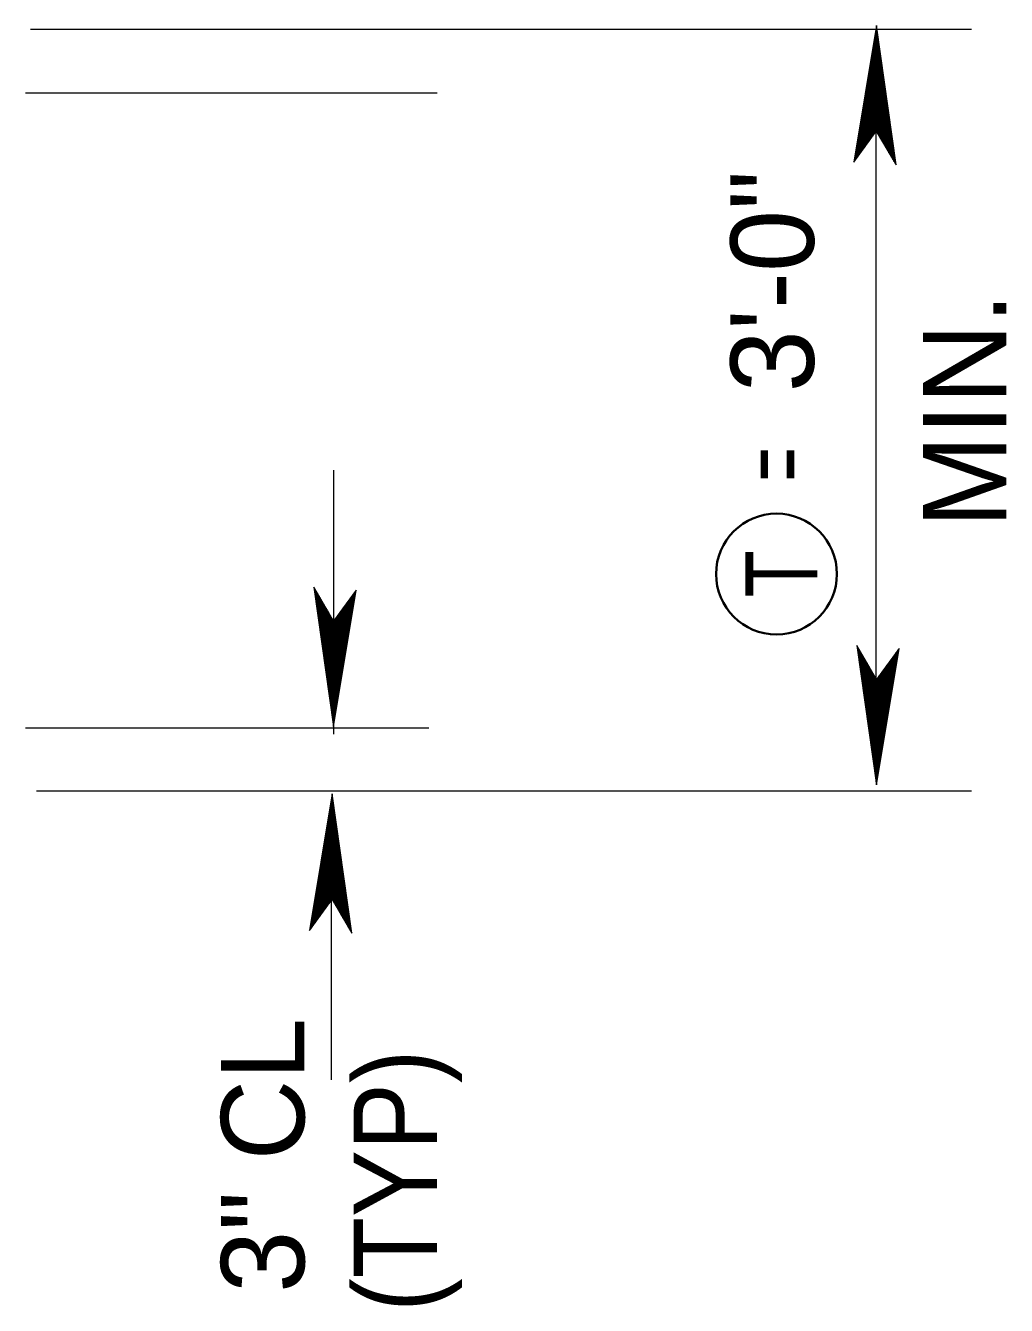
# Model space of a CAD drawing. Extents: x 144 to 252, y 360 to 425.
# Drawn here: x 198.94 to 202.8, y 367.72 to 372.76 of the extents above; entities that cross this region are included whole.
import ezdxf
from ezdxf.enums import TextEntityAlignment as Align

# ---------------------------------------------------------------- set-up
doc = ezdxf.new("R2010")
doc.units = 0
doc.header["$LTSCALE"] = 0.13
for name, color, linetype, lineweight in [('1', 7, 'Continuous', 40), ('16', 7, 'Continuous', 13), ('3', 7, 'Continuous', 13)]:
    doc.layers.add(name, color=color, linetype=linetype, lineweight=lineweight)

msp = doc.modelspace()

# ---------------------------------------------------------------- linework, layer by layer
at = {"layer": '1', "lineweight": 35}
msp.add_circle((201.8951, 370.5969), 0.238, dxfattribs=at)
at = {"layer": '3'}
for p, q in [((198.9573, 372.7427), (201.1462, 372.7427)), ((201.1462, 372.7427), (202.6627, 372.7427)), ((202.2882, 372.7568), (202.1989, 372.2191)), ((202.2875, 372.7423), (202.2012, 372.2223)), ((202.2875, 372.7315), (202.2036, 372.2256)), ((202.2875, 372.7171), (202.2067, 372.2298)), ((202.3624, 372.214), (202.2875, 372.7423)), ((202.3604, 372.2175), (202.2875, 372.7315)), ((202.3577, 372.2221), (202.2875, 372.7171)), ((202.2877, 369.7792), (202.2877, 372.7427)), ((202.2882, 372.3413), (202.2882, 372.7568)), ((202.3659, 372.208), (202.2882, 372.7568)), ((202.2875, 372.7043), (202.2094, 372.2336)), ((202.2875, 372.693), (202.2118, 372.2369)), ((202.2875, 372.6786), (202.215, 372.2412)), ((202.2875, 372.6658), (202.2177, 372.2449)), ((202.3553, 372.2262), (202.2875, 372.7043)), ((202.3553, 372.2262), (202.2875, 372.7043)), ((202.3532, 372.2298), (202.2875, 372.693)), ((202.3505, 372.2344), (202.2875, 372.6786)), ((202.3481, 372.2385), (202.2875, 372.6658)), ((202.2875, 372.6521), (202.2207, 372.249)), ((202.2875, 372.6382), (202.2237, 372.2531)), ((202.2875, 372.625), (202.2265, 372.257)), ((202.3456, 372.2429), (202.2875, 372.6521)), ((202.343, 372.2473), (202.2875, 372.6382)), ((202.3405, 372.2516), (202.2875, 372.625)), ((202.2875, 372.6111), (202.2295, 372.2611)), ((202.2875, 372.5985), (202.2322, 372.2648)), ((202.2875, 372.5871), (202.2347, 372.2682)), ((202.2875, 372.5714), (202.238, 372.2728)), ((202.3378, 372.2561), (202.2875, 372.6111)), ((202.3356, 372.2601), (202.2875, 372.5985)), ((202.3333, 372.2638), (202.2875, 372.5871)), ((202.3305, 372.2688), (202.2875, 372.5714)), ((202.2875, 372.5576), (202.241, 372.2769)), ((202.287, 372.5396), (202.2441, 372.2812)), ((202.287, 372.5257), (202.2471, 372.2853)), ((202.287, 372.5125), (202.2499, 372.2892)), ((202.3237, 372.2804), (202.287, 372.5396)), ((202.3211, 372.2848), (202.287, 372.5257)), ((202.3186, 372.2891), (202.287, 372.5125)), ((202.3278, 372.2732), (202.2875, 372.5576)), ((202.3256, 372.2772), (202.2886, 372.538)), ((198.9383, 372.4917), (200.5583, 372.4917)), ((202.2875, 372.5034), (202.2527, 372.2929)), ((202.2875, 372.4914), (202.2552, 372.2965)), ((202.2875, 372.4776), (202.2583, 372.3006)), ((202.2875, 372.4619), (202.2615, 372.3053)), ((202.3177, 372.2906), (202.2875, 372.5034)), ((202.3155, 372.2945), (202.2875, 372.4914)), ((202.3128, 372.2989), (202.2875, 372.4776)), ((202.31, 372.3039), (202.2875, 372.4619)), ((202.2875, 372.4493), (202.2643, 372.3089)), ((202.2875, 372.4361), (202.2671, 372.3128)), ((202.2875, 372.4241), (202.2697, 372.3164)), ((202.3076, 372.308), (202.2875, 372.4493)), ((202.3051, 372.3123), (202.2875, 372.4361)), ((202.3028, 372.3161), (202.2875, 372.4241)), ((202.2875, 372.4096), (202.2728, 372.3207)), ((202.2875, 372.3957), (202.2757, 372.3248)), ((202.2875, 372.3831), (202.2785, 372.3285)), ((202.2875, 372.3698), (202.2813, 372.3324)), ((202.3002, 372.3207), (202.2875, 372.4096)), ((202.2976, 372.3252), (202.2875, 372.3957)), ((202.2952, 372.3293), (202.2875, 372.3831)), ((202.2922, 372.3345), (202.2886, 372.3596)), ((202.1989, 372.2191), (202.288, 372.3416)), ((202.2875, 372.3584), (202.2837, 372.3358)), ((202.2875, 372.3483), (202.286, 372.3388)), ((202.2906, 372.3372), (202.2875, 372.3584)), ((202.288, 372.3416), (202.3659, 372.208)), ((200.1513, 371.0061), (200.1513, 369.9664)), ((200.0734, 370.5448), (200.1512, 369.9961)), ((200.1513, 370.4112), (200.0734, 370.5448)), ((200.0769, 370.5388), (200.1518, 370.0105)), ((200.0789, 370.5353), (200.1518, 370.0213)), ((200.0816, 370.5308), (200.1518, 370.0358)), ((200.084, 370.5267), (200.1518, 370.0485)), ((200.084, 370.5267), (200.1518, 370.0485)), ((200.0862, 370.523), (200.1518, 370.0598)), ((200.0888, 370.5184), (200.1518, 370.0743)), ((200.0913, 370.5143), (200.1518, 370.087)), ((200.0938, 370.5099), (200.1518, 370.1008)), ((200.0963, 370.5055), (200.1518, 370.1146)), ((200.0988, 370.5012), (200.1518, 370.1278)), ((200.1015, 370.4967), (200.1518, 370.1418)), ((200.1512, 369.9961), (200.2404, 370.5337)), ((200.2404, 370.5337), (200.1513, 370.4112)), ((200.1518, 370.0105), (200.2381, 370.5305)), ((200.1518, 370.0213), (200.2357, 370.5272)), ((200.1518, 370.0358), (200.2326, 370.523)), ((200.1518, 370.0485), (200.2299, 370.5192)), ((200.1518, 370.0598), (200.2275, 370.5159)), ((200.1518, 370.0743), (200.2243, 370.5117)), ((200.1518, 370.087), (200.2216, 370.5079)), ((200.1518, 370.1008), (200.2187, 370.5038)), ((200.1518, 370.1146), (200.2157, 370.4998)), ((200.1518, 370.1278), (200.2128, 370.4958)), ((200.1037, 370.4928), (200.1518, 370.1543)), ((200.106, 370.489), (200.1518, 370.1658)), ((200.1088, 370.484), (200.1518, 370.1814)), ((200.1115, 370.4796), (200.1518, 370.1952)), ((200.1137, 370.4756), (200.1507, 370.2148)), ((200.1157, 370.4724), (200.1523, 370.2132)), ((200.1182, 370.468), (200.1523, 370.2272)), ((200.1207, 370.4638), (200.1523, 370.2403)), ((200.1216, 370.4622), (200.1518, 370.2494)), ((200.1238, 370.4583), (200.1518, 370.2614)), ((200.1265, 370.4539), (200.1518, 370.2752)), ((200.1293, 370.4489), (200.1518, 370.2909)), ((200.1317, 370.4448), (200.1518, 370.3035)), ((200.1518, 370.1418), (200.2098, 370.4917)), ((200.1518, 370.1543), (200.2072, 370.488)), ((200.1518, 370.1658), (200.2047, 370.4846)), ((200.1518, 370.1814), (200.2013, 370.48)), ((200.1518, 370.1952), (200.1983, 370.4759)), ((200.1518, 370.2494), (200.1867, 370.4599)), ((200.1518, 370.2614), (200.1841, 370.4563)), ((200.1518, 370.2752), (200.1811, 370.4522)), ((200.1518, 370.2909), (200.1778, 370.4476)), ((200.1523, 370.2132), (200.1952, 370.4717)), ((200.1523, 370.2272), (200.1923, 370.4675)), ((200.1523, 370.2403), (200.1894, 370.4637)), ((200.1342, 370.4406), (200.1518, 370.3168)), ((200.1365, 370.4367), (200.1518, 370.3288)), ((200.1392, 370.4321), (200.1518, 370.3433)), ((200.1418, 370.4277), (200.1518, 370.3571)), ((200.1441, 370.4236), (200.1518, 370.3698)), ((200.1472, 370.4183), (200.1507, 370.3932)), ((200.1488, 370.4157), (200.1518, 370.3944)), ((200.1512, 370.4115), (200.1512, 369.9961)), ((200.1518, 370.3035), (200.1751, 370.4439)), ((200.1518, 370.3168), (200.1722, 370.44)), ((200.1518, 370.3288), (200.1696, 370.4364)), ((200.1518, 370.3433), (200.1666, 370.4322)), ((200.1518, 370.3571), (200.1636, 370.428)), ((200.1518, 370.3698), (200.1608, 370.4243)), ((200.1518, 370.383), (200.158, 370.4204)), ((200.1518, 370.3944), (200.1556, 370.417)), ((200.1518, 370.4046), (200.1533, 370.414)), ((202.2111, 370.3149), (202.2888, 369.7662)), ((202.289, 370.1813), (202.2111, 370.3149)), ((202.2146, 370.3089), (202.2895, 369.7806)), ((202.2166, 370.3054), (202.2895, 369.7914)), ((202.2192, 370.3008), (202.2895, 369.8058)), ((202.2217, 370.2967), (202.2895, 369.8186)), ((202.2217, 370.2967), (202.2895, 369.8186)), ((202.2888, 369.7662), (202.3781, 370.3038)), ((202.3781, 370.3038), (202.289, 370.1813)), ((202.2895, 369.7806), (202.3757, 370.3006)), ((202.2895, 369.7914), (202.3734, 370.2973)), ((202.2238, 370.2931), (202.2895, 369.8299)), ((202.2265, 370.2885), (202.2895, 369.8443)), ((202.2289, 370.2844), (202.2895, 369.8571)), ((202.2314, 370.28), (202.2895, 369.8708)), ((202.234, 370.2756), (202.2895, 369.8847)), ((202.2365, 370.2713), (202.2895, 369.8979)), ((202.2392, 370.2668), (202.2895, 369.9118)), ((202.2414, 370.2628), (202.2895, 369.9244)), ((202.2437, 370.2591), (202.2895, 369.9358)), ((202.2465, 370.2541), (202.2895, 369.9515)), ((202.2492, 370.2497), (202.2895, 369.9653)), ((202.2514, 370.2457), (202.2884, 369.9849)), ((202.2895, 369.8058), (202.3702, 370.2931)), ((202.2895, 369.8186), (202.3676, 370.2893)), ((202.2895, 369.8299), (202.3652, 370.286)), ((202.2895, 369.8443), (202.362, 370.2817)), ((202.2895, 369.8571), (202.3593, 370.278)), ((202.2895, 369.8708), (202.3563, 370.2739)), ((202.2895, 369.8847), (202.3533, 370.2698)), ((202.2895, 369.8979), (202.3505, 370.2659)), ((202.2895, 369.9118), (202.3475, 370.2618)), ((202.2895, 369.9244), (202.3448, 370.2581)), ((202.2895, 369.9358), (202.3423, 370.2547)), ((202.2895, 369.9515), (202.339, 370.2501)), ((202.2895, 369.9653), (202.336, 370.246)), ((202.2533, 370.2425), (202.29, 369.9833)), ((202.2559, 370.2381), (202.29, 369.9973)), ((202.2584, 370.2338), (202.29, 370.0104)), ((202.2592, 370.2323), (202.2895, 370.0195)), ((202.2615, 370.2284), (202.2895, 370.0315)), ((202.2642, 370.224), (202.2895, 370.0453)), ((202.267, 370.219), (202.2895, 370.061)), ((202.2694, 370.2149), (202.2895, 370.0736)), ((202.2719, 370.2107), (202.2895, 370.0868)), ((202.2742, 370.2068), (202.2895, 370.0988)), ((202.2768, 370.2022), (202.2895, 370.1133)), ((202.2794, 370.1977), (202.2895, 370.1272)), ((202.2817, 370.1937), (202.2895, 370.1398)), ((202.2895, 370.0195), (202.3243, 370.23)), ((202.2895, 370.0315), (202.3217, 370.2264)), ((202.2895, 370.0453), (202.3187, 370.2223)), ((202.2895, 370.061), (202.3155, 370.2177)), ((202.2895, 370.0736), (202.3127, 370.214)), ((202.2895, 370.0868), (202.3099, 370.2101)), ((202.2895, 370.0988), (202.3072, 370.2065)), ((202.2895, 370.1133), (202.3042, 370.2022)), ((202.2895, 370.1272), (202.3012, 370.1981)), ((202.2895, 370.1398), (202.2985, 370.1944)), ((202.29, 369.9833), (202.3329, 370.2417)), ((202.29, 369.9973), (202.3299, 370.2376)), ((202.29, 370.0104), (202.3271, 370.2337)), ((202.2848, 370.1884), (202.2884, 370.1633)), ((202.2864, 370.1857), (202.2895, 370.1645)), ((202.2888, 370.1816), (202.2888, 369.7662)), ((202.2895, 370.1531), (202.2957, 370.1905)), ((202.2895, 370.1645), (202.2933, 370.1871)), ((202.2895, 370.1747), (202.291, 370.1841)), ((198.9383, 369.9917), (200.5262, 369.9917)), ((198.9815, 369.7427), (200.5262, 369.7427)), ((199.1858, 369.7427), (200.087, 369.7427)), ((200.087, 369.7427), (201.1462, 369.7427)), ((201.1462, 369.7427), (202.6627, 369.7427)), ((200.1454, 369.7315), (200.0562, 369.1938)), ((200.1447, 369.7171), (200.0585, 369.1971)), ((200.1447, 369.7063), (200.0608, 369.2003)), ((200.1447, 369.6918), (200.064, 369.2046)), ((200.2197, 369.1887), (200.1447, 369.7171)), ((200.2177, 369.1923), (200.1447, 369.7063)), ((200.215, 369.1968), (200.1447, 369.6918)), ((200.1454, 369.3161), (200.1454, 369.7315)), ((200.2232, 369.1827), (200.1454, 369.7315)), ((200.1447, 369.6791), (200.0667, 369.2083)), ((200.1447, 369.6678), (200.0691, 369.2117)), ((200.1447, 369.6533), (200.0722, 369.2159)), ((200.1447, 369.6406), (200.075, 369.2197)), ((200.1422, 368.6049), (200.1422, 369.6867)), ((200.2126, 369.2009), (200.1447, 369.6791)), ((200.2126, 369.2009), (200.1447, 369.6791)), ((200.2104, 369.2046), (200.1447, 369.6678)), ((200.2078, 369.2092), (200.1447, 369.6533)), ((200.2053, 369.2132), (200.1447, 369.6406)), ((200.1447, 369.6268), (200.0779, 369.2237)), ((200.1447, 369.613), (200.0809, 369.2278)), ((200.1447, 369.5997), (200.0837, 369.2317)), ((200.2028, 369.2177), (200.1447, 369.6268)), ((200.2002, 369.2221), (200.1447, 369.613)), ((200.1977, 369.2263), (200.1447, 369.5997)), ((200.1447, 369.5858), (200.0867, 369.2358)), ((200.1447, 369.5732), (200.0894, 369.2396)), ((200.1447, 369.5618), (200.0919, 369.243)), ((200.1447, 369.5462), (200.0952, 369.2476)), ((200.1951, 369.2308), (200.1447, 369.5858)), ((200.1928, 369.2348), (200.1447, 369.5732)), ((200.1906, 369.2386), (200.1447, 369.5618)), ((200.1877, 369.2436), (200.1447, 369.5462)), ((200.1447, 369.5323), (200.0983, 369.2517)), ((200.1442, 369.5143), (200.1013, 369.2559)), ((200.1442, 369.5004), (200.1043, 369.2601)), ((200.1442, 369.4872), (200.1072, 369.2639)), ((200.1809, 369.2552), (200.1442, 369.5143)), ((200.1783, 369.2596), (200.1442, 369.5004)), ((200.1758, 369.2638), (200.1442, 369.4872)), ((200.1851, 369.248), (200.1447, 369.5323)), ((200.1828, 369.252), (200.1458, 369.5127)), ((200.1447, 369.4782), (200.1099, 369.2677)), ((200.1447, 369.4662), (200.1125, 369.2713)), ((200.1447, 369.4523), (200.1155, 369.2753)), ((200.1447, 369.4367), (200.1188, 369.28)), ((200.175, 369.2653), (200.1447, 369.4782)), ((200.1727, 369.2692), (200.1447, 369.4662)), ((200.1701, 369.2737), (200.1447, 369.4523)), ((200.1672, 369.2787), (200.1447, 369.4367)), ((200.1447, 369.4241), (200.1215, 369.2837)), ((200.1447, 369.4108), (200.1243, 369.2876)), ((200.1447, 369.3988), (200.127, 369.2912)), ((200.1648, 369.2827), (200.1447, 369.4241)), ((200.1623, 369.287), (200.1447, 369.4108)), ((200.1601, 369.2908), (200.1447, 369.3988)), ((200.1447, 369.3843), (200.13, 369.2954)), ((200.1447, 369.3705), (200.133, 369.2996)), ((200.1447, 369.3578), (200.1358, 369.3032)), ((200.1447, 369.3446), (200.1386, 369.3072)), ((200.1574, 369.2955), (200.1447, 369.3843)), ((200.1548, 369.2999), (200.1447, 369.3705)), ((200.1525, 369.304), (200.1447, 369.3578)), ((200.0562, 369.1938), (200.1453, 369.3163)), ((200.1447, 369.3332), (200.141, 369.3106)), ((200.1447, 369.323), (200.1432, 369.3136)), ((200.1478, 369.3119), (200.1447, 369.3332)), ((200.1453, 369.3163), (200.2232, 369.1827)), ((200.1494, 369.3092), (200.1458, 369.3343))]:
    msp.add_line(p, q, dxfattribs=at)

# ---------------------------------------------------------------- texts
at = {"layer": '1'}
for s, width, p in [('=', 0.6, (202.0342, 371.0289)), ('T', 0.8, (202.0556, 370.5981))]:
    msp.add_text(s, height=0.2833, rotation=90, dxfattribs=dict(at, width=width)).set_placement(p, align=Align.CENTER)
at = {"layer": '16'}
for s, p in [('3\'-0"', (202.042, 371.7497)), ('MIN.', (202.8003, 371.2416))]:
    msp.add_text(s, height=0.3281, rotation=90, dxfattribs=at).set_placement(p, align=Align.CENTER)
msp.add_text('3" CL', height=0.3281, rotation=90, dxfattribs=at).set_placement((200.0359, 368.8489), align=Align.RIGHT)
at = {"layer": '16', "width": 0.9}
msp.add_text('(TYP)', height=0.3281, rotation=90, dxfattribs=at).set_placement((200.5582, 368.7232), align=Align.RIGHT)

doc.saveas('drawing.dxf')
